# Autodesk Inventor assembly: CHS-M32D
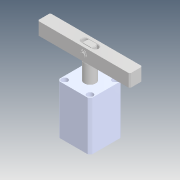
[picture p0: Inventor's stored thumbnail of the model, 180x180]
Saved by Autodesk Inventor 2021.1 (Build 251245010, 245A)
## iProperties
Created: 2020-02
Part Number: CHS-M32D
Description: STEP AP214
Document SubType Name: Assembly
Designer: user
Title: chs-m32d_asm.STEP
Revision Number: ÈÎºÎ
Sending System: SolidWorks 2016
Preprocessor: SwSTEP 2.0
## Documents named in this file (6)
- D:\Vault_2016\Projekty\Clamptek\Hydraulic\CHS\CHS-32\Inventor\CHS-M32D\CHS-M32D.iam
- D:\Vault_2016\Projekty\Clamptek\Hydraulic\CHS\CHS-32\Inventor\CHS-M32D\CHS-32D-02_4_1.ipt
- D:\Vault_2016\Projekty\Clamptek\Hydraulic\CHS\CHS-32\Inventor\CHS-M32D\CHS-32D-01_5.ipt
- D:\Vault_2016\Projekty\Clamptek\Hydraulic\CHS\CHS-32\Inventor\CHS-M32D\CHS-M32BT.ipt
- D:\Vault_2016\Projekty\Clamptek\Hydraulic\CHS\CHS-32\Inventor\CHS-M32D\Öá8µ²È¦.ipt
- D:\Vault_2016\Projekty\Clamptek\Hydraulic\CHS\CHS-32\Inventor\CHS-M32D\Xiaozhou.ipt
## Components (6 placed, 6 different names)
1. CHS-32D-02_4_1_1
2. CHS-32D-01_5_2
3. CHS-M32BT_3
4. Öá8µ²È¦_4
5. Xiaozhou_5
6. Öá8µ²È¦_6
